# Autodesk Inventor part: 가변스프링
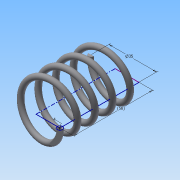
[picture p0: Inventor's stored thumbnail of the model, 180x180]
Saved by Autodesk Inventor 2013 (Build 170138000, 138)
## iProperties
Created: 2015-03
Part Number: 가변스프링
Material: 강철, 탄소
Document SubType Name: Modeling
Designer: Administrator
Density: 7.87 g/cm^3
Mass: 47.9648 g
Surface Area: 62.0176 cm^2
Volume: 6.09464 cm^3
Author: Administrator
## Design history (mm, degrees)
sketch "스케치1"
  geometry: L1 (0, 0)-(17.5, 0); L2 (17.5, 0)-(17.5, 43.5); L3 (17.5, 43.5)-(0, 43.5); L4 (0, 43.5)-(0, 0); C1 r 2 at (17.5, 0)
  constraints: 8 end point, 2 parallel, 1 centre point, 1 coincident, 1 horizontal, 1 perpendicular
  dimensions: "d0" = 35 diameter of L2 L4; "d2" = 43.5 distance of L1.end L2.end (derived); "d3" = 4 diameter of C1
feature "코일1" pitch "d4" = 10; turns "d6" = 4.5; dims "d5" = 43.5 (= d2), "d7" = 0, angle "d8" = 90 deg, angle "d9" = 90 deg, "d10" = 0, "d11" = 0
node "작업 평면1"
sketch "스케치2"
  geometry: L1 (-19.5, 0)-(-15.5, 0) reference; 1 further point
  constraints: 1 horizontal alignment
extrude "돌출1" cut sketch "스케치2" stored distance "d13" = 10; taper "d14" = 0 deg
node "작업 평면2"
sketch "스케치3"
  geometry: L1 (15.5, 0)-(19.5, 0) reference; 1 further point
  constraints: 1 horizontal alignment
extrude "돌출2" cut sketch "스케치3" stored distance "d16" = 10; taper "d17" = 0 deg
node "솔리드1"
node "절단 모서리 투영1"
node "절단 모서리 투영2"
other parameters: "d12" = 0, "d15" = 43.5 (= d2)
